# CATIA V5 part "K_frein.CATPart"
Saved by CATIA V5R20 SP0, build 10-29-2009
Part number: frein
Bounding box of the stored display mesh (mm): x -9 to 9, y 692.462 to 822.462, z 12.199 to 92.194
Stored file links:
  G:\Khaled_CFAO_2011\SIL\SIL_GR2\ahabrial\ahabrial\Khaled\CAD_ThinkMOTION\K_frein.CATPart
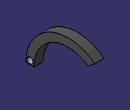
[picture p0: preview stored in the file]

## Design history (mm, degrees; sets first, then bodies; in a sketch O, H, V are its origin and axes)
Parameters
  Epaisseur_frein = 15 mm
  Largeur_frein = 18 mm
Body1 (main body)
  Sketch1 on yz-plane, origin (0, 0, 0), H (0, 1, 0), V (0, 0, 1)
    arc A1 centre (772.4618, 12.1988) radius 80 from (822.4618, 74.6488) to (692.4618, 12.1988) ccw
    arc A2 centre (772.4618, 12.1988) radius 65 from (810.257, 65.081) to (707.4618, 12.1988) ccw
    point P5 (707.4618, 12.1988)
    line L1 (707.4618, 12.1988) -> (692.4618, 12.1988)
    line L2 (822.4618, 74.6488) -> (810.257, 65.081)
    axis line L3 (699.9618, 0) -> (699.9618, 100)
    point P6 (699.9618, 0)
    length L1 = 15 {= Epaisseur_frein}
    distance P5 L3 = 7.5 {= Epaisseur_frein /2}
    horizontal: L1 H
    coincidence: P6 H
    vertical: L3 V
  Pad1: profile Sketch1, direction (1, 0, 0), length 9 {= Largeur_frein /2}, mirrored extent
  Sketch2 on end face of Pad1, origin (9, 0, 0), H (0, 1, 0), V (0, 0, 1)
    circle A1 centre (699.9618, 19.6988) radius 5.625
    point P1 (699.9618, 19.6988)
    reference projected line E1 (692.4618, 12.1988) -> (707.4618, 12.1988) from edge [face of Pad1 from Sketch1.L1 | end face of Pad1]
    axis line L1 (692.4618, 12.1988) -> (692.4618, 52.1988)
    point P2 (692.4618, 12.1988)
    reference projected point E2 (692.4618, 12.1988) from vertex [face of Pad1 from Sketch1.L1 | end face of Pad1 | face of Pad1 from Sketch1.A1]
    radius A1 = 5.625 {= (Epaisseur_frein /(4/3))/2}
    distance E1 P1 = 7.5 {= Epaisseur_frein /2}
    distance P1 L1 = 7.5 {= Epaisseur_frein /2}
    vertical: L1 V
    coincidence: P2 E2
  Pocket1: profile Sketch2, direction (-1, 0, 0), through (limit type 6)
  Point1 "Point.1_origine": (0, 0, 0)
